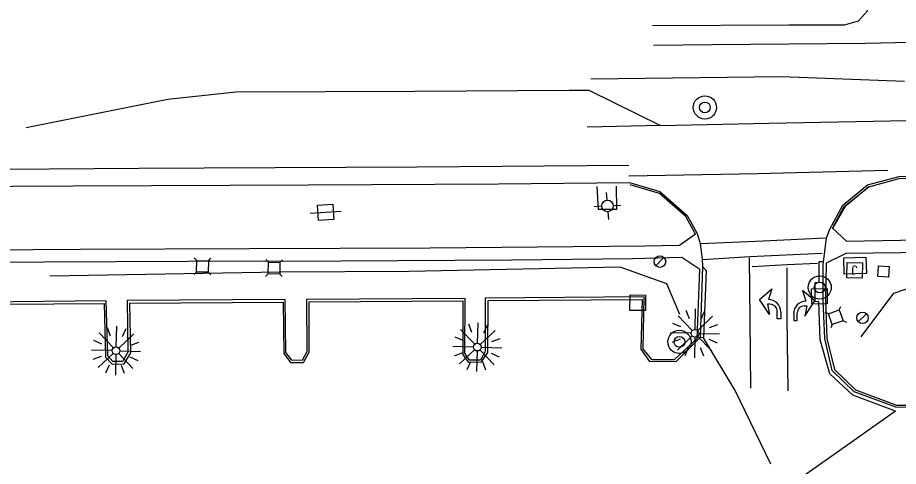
# Model space of a CAD drawing. Extents: x 4711259 to 4716401, y 890074 to 892728.
# Drawn here: x 4711416.6 to 4711702.3, y 891219.7 to 891365.1 of the extents above; entities that cross this region are included whole.
import ezdxf

# ---------------------------------------------------------------- set-up
doc = ezdxf.new("R2010")
doc.units = 0
for name, color, linetype in [('E_HY_STORM_Inlet', 7, 'Continuous'), ('E_HY_STORM_MH', 7, 'Continuous'), ('E_RDWY_ROAD_Curb', 7, 'Continuous'), ('E_RDWY_ROAD_EdgeAsph', 7, 'Continuous'), ('E_RDWY_ROAD_EdgeConc', 7, 'Continuous'), ('E_RDWY_ROAD_Sidewalk', 7, 'Continuous'), ('E_RDWY_ROAD_Striping', 7, 'Continuous'), ('E_RDWY_ROAD_TBofCurb', 7, 'Continuous'), ('E_TERR_DTM_BrkLines', 7, 'Continuous'), ('E_TRAF_ILLUM_Poles', 7, 'Continuous'), ('E_UTIL_COMM_General', 7, 'Continuous'), ('E_UTIL_ELEC_GENERAL', 7, 'Continuous'), ('E_UTIL_ELEC_POLE', 7, 'Continuous'), ('E_UTIL_WTR_General', 7, 'Continuous')]:
    doc.layers.add(name, color=color, linetype=linetype)

msp = doc.modelspace()

# ---------------------------------------------------------------- linework, layer by layer
at = {"layer": 'E_HY_STORM_Inlet'}
for p, q in [((4711676.68, 891274.75), (4711676.68, 891274.75)), ((4711617.76, 891272.68), (4711617.76, 891272.68))]:
    msp.add_line(p, q, dxfattribs=at)
for points in [[(4711674.13, 891277.2), (4711679.13, 891277.3), (4711679.23, 891272.3), (4711674.23, 891272.21)], [(4711615.3, 891275.22), (4711620.3, 891275.13), (4711620.21, 891270.13), (4711615.21, 891270.22)]]:
    msp.add_lwpolyline(points, close=True, dxfattribs=at)
at = {"layer": 'E_HY_STORM_MH'}
for centre, radius in [((4711639.52, 891335.97), 3.75), ((4711639.52, 891335.97), 1.76), ((4711676.75, 891277.63), 3.75), ((4711676.75, 891277.63), 1.76), ((4711631.27, 891260), 3.75), ((4711631.27, 891260), 1.76)]:
    msp.add_circle(centre, radius, dxfattribs=at)
at = {"layer": 'E_RDWY_ROAD_Curb'}
for points in [[(4711677.89, 891285), (4711678.92, 891293.73), (4711680.03, 891296.58), (4711684.3, 891304.36), (4711692.29, 891310.9), (4711702.5, 891313.59), (4711725.75, 891314.23), (4711752.78, 891314.68), (4711806.62, 891316.06), (4711863.71, 891317.72), (4711920.16, 891319.09), (4711978.72, 891320.62), (4712033.32, 891322.35), (4712043.64, 891320.44), (4712051.78, 891316.35), (4712057.43, 891308.73), (4712059.79, 891302.94), (4712060.64, 891297.72), (4712061.23, 891292.43), (4712061.25, 891285.91), (4712059.69, 891272.02), (4712042.09, 891234.96)], [(4711336.39, 891310.08), (4711434.66, 891310.58), (4711510.87, 891310.89), (4711572.62, 891311.17), (4711615.1, 891311.7)], [(4711615.1, 891311.7), (4711624.96, 891308.73), (4711633.75, 891300.95), (4711636.98, 891295.13), (4711637.96, 891291.85), (4711638.62, 891286.7), (4711638.71, 891284.42), (4711637.98, 891261.39), (4711630.13, 891253.52), (4711621.59, 891253.6)], [(4711708.13, 891238.7), (4711701.49, 891238.83), (4711687.96, 891243.76), (4711680.82, 891250.74), (4711678.38, 891261.09), (4711677.88, 891273.18), (4711677.89, 891285)], [(4711395.75, 891272.12), (4711444.67, 891272.45), (4711445.13, 891255.08), (4711447.26, 891252.82), (4711451.17, 891252.94), (4711453.3, 891256.43), (4711453.02, 891272.5), (4711502.79, 891272.88), (4711503.01, 891256.28), (4711505.14, 891253.37), (4711509.38, 891253.31), (4711511.22, 891256.72), (4711511.23, 891273.02), (4711561.06, 891273.28), (4711561, 891255.89), (4711562.79, 891253.43), (4711567.13, 891253.58), (4711569.11, 891256.58), (4711569.24, 891273.42), (4711619.16, 891273.78), (4711618.73, 891257.6), (4711621.59, 891253.6)]]:
    msp.add_lwpolyline(points, dxfattribs=at)
at = {"layer": 'E_RDWY_ROAD_EdgeAsph'}
for points in [[(4711622.49, 891362.56), (4711666.76, 891362.73), (4711684.78, 891362.8), (4711689.34, 891364.01), (4711692.25, 891367.31), (4711693.53, 891374.56), (4711703.95, 891374.38), (4711705.24, 891368.87), (4711709.96, 891362.68), (4711776.96, 891364.6), (4711835.98, 891366.03), (4711881.41, 891367.59), (4711919.85, 891369), (4711975.05, 891370.75), (4712029.86, 891371.24)], [(4711701.39, 891237.5), (4711679.61, 891222.19), (4711662.18, 891210.05), (4711661.02, 891210.07)]]:
    msp.add_lwpolyline(points, dxfattribs=at)
at = {"layer": 'E_RDWY_ROAD_EdgeConc'}
for points in [[(4711610.72, 891310.43), (4711610.84, 891302.85), (4711604.98, 891302.94), (4711604.63, 891310.31)], [(4711638.71, 891284.42), (4711639.99, 891283.15), (4711639.09, 891261.33), (4711637.98, 891261.39)], [(4711701.39, 891237.5), (4711687.47, 891242.73), (4711680.02, 891249.68), (4711676.96, 891260.68), (4711676.52, 891273.03), (4711675.29, 891273.13), (4711675.33, 891279.25), (4711676.55, 891279.34), (4711676.57, 891286.07), (4711677.74, 891286.05)]]:
    msp.add_lwpolyline(points, dxfattribs=at)
msp.add_lwpolyline([(4711691.9, 891282.19), (4711684.72, 891281.98), (4711684.56, 891287.28), (4711691.74, 891287.49)], close=True, dxfattribs=at)
at = {"layer": 'E_RDWY_ROAD_Sidewalk'}
for points in [[(4711680.94, 891296.87), (4711685.45, 891292.66), (4711703.01, 891292.95), (4711756.99, 891293.66), (4711817.64, 891294.79), (4711872.66, 891296.02), (4711927.41, 891297.55), (4711987.49, 891299.53), (4712044.77, 891301.24), (4712054.16, 891301.77), (4712056.9, 891308.38)], [(4712050.78, 891266.23), (4712053.25, 891271.6), (4712055.37, 891280.57), (4712055.29, 891292.27), (4712055, 891297.78), (4712049.68, 891297.66), (4711987.64, 891295.63), (4711929.81, 891293.64), (4711872.89, 891292.06), (4711812.57, 891290.78), (4711757.77, 891289.78), (4711703.21, 891288.9), (4711685.19, 891288.65), (4711678.83, 891285.53)], [(4711636.46, 891294.88), (4711631.24, 891291.26), (4711620.01, 891291.07)], [(4711678.57, 891293.62), (4711658.43, 891292.69), (4711638.33, 891291.79)], [(4711620.01, 891291.07), (4711550.39, 891290.38), (4711491.78, 891290.18), (4711436.87, 891289.98), (4711406.11, 891289.74), (4711362.14, 891289.55)], [(4711620.16, 891287.14), (4711632, 891287.42), (4711637.92, 891283.58)], [(4711638.8, 891286.74), (4711654.11, 891287.68), (4711677.56, 891288.76)], [(4711336.87, 891255.64), (4711335.57, 891258.42), (4711335.29, 891268.88), (4711334.66, 891285.1), (4711401.76, 891285.78), (4711471.79, 891286.18), (4711521.53, 891286.27), (4711576.93, 891286.64), (4711616.2, 891287.07), (4711620.16, 891287.14)]]:
    msp.add_lwpolyline(points, dxfattribs=at)
at = {"layer": 'E_RDWY_ROAD_Striping'}
for p, q in [((4711657.28, 891273.74), (4711661.22, 891277.2)), ((4711661.22, 891277.2), (4711660.13, 891273.73)), ((4711675.13, 891273.25), (4711671.15, 891276.68)), ((4711671.15, 891276.68), (4711672.27, 891273.22)), ((4711660.5, 891268.82), (4711657.28, 891273.74)), ((4711671.95, 891268.31), (4711675.13, 891273.25)), ((4711660.7, 891272.21), (4711659.84, 891272.21)), ((4711659.84, 891272.21), (4711660.5, 891268.82)), ((4711671.72, 891271.69), (4711672.57, 891271.7)), ((4711672.57, 891271.7), (4711671.95, 891268.31)), ((4711662.98, 891267.44), (4711662.98, 891269.92)), ((4711664.12, 891267.44), (4711662.98, 891267.44)), ((4711664.13, 891269.63), (4711664.12, 891267.44)), ((4711668.32, 891269.08), (4711668.34, 891266.89)), ((4711669.48, 891266.91), (4711669.46, 891269.38)), ((4711668.34, 891266.89), (4711669.48, 891266.91))]:
    msp.add_line(p, q, dxfattribs=at)
for points in [[(4712033.23, 891366), (4711976.49, 891364.57), (4711912.7, 891362.48), (4711863.23, 891361.09), (4711806.05, 891359.63), (4711750.14, 891358.03), (4711691.65, 891356.7), (4711641.88, 891356.32), (4711622.85, 891356.1)], [(4711602.05, 891341.43), (4711595.51, 891341.52), (4711545.33, 891341.09), (4711487.42, 891340.98), (4711465.31, 891338.52), (4711419.36, 891329.32)], [(4711602.05, 891341.43), (4711625.17, 891330.14)], [(4711625.17, 891330.14), (4711601.34, 891329.6)], [(4711269.83, 891315.08), (4711322.53, 891315.28), (4711397.46, 891315.84), (4711456.03, 891316.25), (4711477.12, 891316.43), (4711546.25, 891316.78), (4711614.88, 891317.24)], [(4711654.4, 891244.96), (4711654.2, 891267.12), (4711654.03, 891287.21)], [(4711676.09, 891285.4), (4711666.16, 891284.96), (4711654.85, 891284.32)], [(4711666.07, 891284.04), (4711666.11, 891267.61), (4711666.41, 891244.17)]]:
    msp.add_lwpolyline(points, dxfattribs=at)
for centre, radius, start, end in [((4711660.03, 891269.64), 4.1, 359.9112, 88.579), ((4711672.41, 891269.13), 4.1, 91.9545, 180.6222), ((4711660.7, 891269.92), 2.29, 359.9078, 89.9018), ((4711671.74, 891269.41), 2.29, 90.6317, 180.6256)]:
    msp.add_arc(centre, radius, start, end, dxfattribs=at)
at = {"layer": 'E_RDWY_ROAD_TBofCurb'}
for p, q in [((4711692.74, 891310.26), (4711684.89, 891303.73)), ((4711684.89, 891303.73), (4711680.94, 891296.87))]:
    msp.add_line(p, q, dxfattribs=at)
for points in [[(4711680.94, 891296.87), (4711684.71, 891303.85), (4711692.73, 891310.28), (4711702.57, 891312.99), (4711755.12, 891313.91), (4711827.99, 891315.91), (4711883.3, 891317.38), (4711938.22, 891318.67), (4711998.29, 891320.44), (4712033.48, 891321.46), (4712043.24, 891319.87), (4712051.19, 891316)], [(4711636.46, 891294.88), (4711633.35, 891300.64), (4711624.75, 891308.1), (4711615.29, 891310.88)], [(4711678.83, 891285.53), (4711678.61, 891273.44), (4711679.02, 891261.06), (4711681.52, 891251.07), (4711688.38, 891244.51), (4711701.66, 891239.49), (4711707.68, 891239.44), (4711709.96, 891240.83), (4711711.12, 891243.96), (4711711.6, 891259.16), (4711762.73, 891258.56)], [(4711622.28, 891254.31), (4711629.69, 891254.34), (4711636.97, 891261.09), (4711637.92, 891283.58)], [(4711622.28, 891254.31), (4711619.56, 891257.73), (4711619.83, 891274.63), (4711568.22, 891274.18), (4711568.24, 891256.9), (4711566.73, 891254.08), (4711563.18, 891254.03), (4711561.65, 891256.38), (4711561.8, 891274.11), (4711510.27, 891273.75), (4711510.4, 891256.81), (4711508.96, 891254), (4711505.58, 891254.08), (4711503.6, 891256.61), (4711503.42, 891273.7), (4711452.13, 891273.38), (4711452.36, 891256.66), (4711452.37, 891256.65), (4711450.67, 891253.69), (4711447.55, 891253.68), (4711445.89, 891255.53), (4711445.3, 891273.26), (4711394.99, 891272.77)]]:
    msp.add_lwpolyline(points, dxfattribs=at)
at = {"layer": 'E_TERR_DTM_BrkLines'}
for points in [[(4711704.21, 891344.39), (4711664.41, 891345.94), (4711602.57, 891345.09)], [(4711625.17, 891330.14), (4711660.28, 891330.85), (4711705.38, 891331.75)], [(4711698.81, 891315.54), (4711656.55, 891314.47), (4711614.91, 891313.71)], [(4711631.45, 891268.86), (4711627.19, 891278.85), (4711612.04, 891284.17), (4711543.66, 891282.82), (4711501.82, 891282.61), (4711427.09, 891281.33)], [(4711690.22, 891261.69), (4711700.8, 891275.77), (4711716.75, 891281.33), (4711771.69, 891282.14), (4711826.88, 891280.82), (4711878.94, 891280.02), (4711938.44, 891278.06), (4711946.19, 891277.02)], [(4711660.92, 891220.4), (4711649.32, 891244.25), (4711639.09, 891261.33)]]:
    msp.add_lwpolyline(points, dxfattribs=at)
at = {"layer": 'E_TRAF_ILLUM_Poles'}
for p, q in [((4711634.49, 891267.51), (4711633.46, 891270.17)), ((4711636.34, 891264.03), (4711636.46, 891270.7)), ((4711635.45, 891263.68), (4711630.82, 891268.48)), ((4711637.22, 891263.65), (4711642.01, 891268.28)), ((4711638.37, 891267.42), (4711639.52, 891270.02)), ((4711446.79, 891261.87), (4711445.79, 891264.54)), ((4711448.6, 891258.38), (4711448.8, 891265.04)), ((4711563.96, 891263.04), (4711562.97, 891265.71)), ((4711565.77, 891259.55), (4711565.97, 891266.21)), ((4711567.84, 891262.91), (4711569.02, 891265.5)), ((4711631.68, 891264.84), (4711629.08, 891265.99)), ((4711641.04, 891264.61), (4711643.7, 891265.64)), ((4711447.7, 891258.04), (4711443.13, 891262.89)), ((4711449.47, 891257.98), (4711454.32, 891262.56)), ((4711450.67, 891261.74), (4711451.85, 891264.33)), ((4711561.12, 891260.4), (4711558.53, 891261.58)), ((4711564.88, 891259.21), (4711560.31, 891264.06)), ((4711566.64, 891259.15), (4711571.5, 891263.73)), ((4711635.07, 891262.81), (4711628.4, 891262.93)), ((4711635.42, 891261.92), (4711630.62, 891257.29)), ((4711636.29, 891261.53), (4711636.17, 891254.87)), ((4711637.18, 891261.88), (4711641.81, 891257.09)), ((4711637.57, 891262.76), (4711644.23, 891262.64)), ((4711443.95, 891259.23), (4711441.36, 891260.41)), ((4711453.31, 891258.9), (4711455.98, 891259.9)), ((4711570.48, 891260.07), (4711573.15, 891261.07)), ((4711628.93, 891259.93), (4711631.59, 891260.96)), ((4711643.56, 891259.58), (4711640.95, 891260.73)), ((4711447.31, 891257.16), (4711440.65, 891257.36)), ((4711447.65, 891256.27), (4711442.8, 891251.7)), ((4711448.52, 891255.88), (4711448.33, 891249.21)), ((4711449.42, 891256.22), (4711453.99, 891251.37)), ((4711449.81, 891257.09), (4711456.48, 891256.89)), ((4711564.49, 891258.33), (4711557.82, 891258.53)), ((4711558.32, 891255.53), (4711560.99, 891256.52)), ((4711564.83, 891257.44), (4711559.97, 891252.87)), ((4711565.7, 891257.05), (4711565.5, 891250.38)), ((4711566.59, 891257.39), (4711571.17, 891252.54)), ((4711566.98, 891258.26), (4711573.65, 891258.06)), ((4711572.94, 891255.01), (4711570.35, 891256.19)), ((4711633.11, 891255.54), (4711634.26, 891258.15)), ((4711639.17, 891255.4), (4711638.14, 891258.06)), ((4711441.15, 891254.36), (4711443.82, 891255.36)), ((4711455.76, 891253.84), (4711453.18, 891255.02)), ((4711562.45, 891251.09), (4711563.63, 891253.68)), ((4711568.5, 891250.88), (4711567.51, 891253.55)), ((4711445.28, 891249.93), (4711446.46, 891252.51)), ((4711451.33, 891249.71), (4711450.33, 891252.38))]:
    msp.add_line(p, q, dxfattribs=at)
for centre in [(4711636.32, 891262.78), (4711565.74, 891258.3), (4711448.56, 891257.13)]:
    msp.add_circle(centre, 1.25, dxfattribs=at)
at = {"layer": 'E_UTIL_COMM_General'}
msp.add_lwpolyline([(4711699.32, 891284.42), (4711699.07, 891280.93), (4711695.58, 891281.18), (4711695.83, 891284.67)], close=True, dxfattribs=at)
at = {"layer": 'E_UTIL_ELEC_GENERAL'}
msp.add_lwpolyline([(4711685.67, 891285.73), (4711690.67, 891285.64), (4711690.57, 891280.64), (4711685.57, 891280.73)], close=True, dxfattribs=at)
at = {"layer": 'E_UTIL_ELEC_POLE'}
msp.add_line((4711511.54, 891301.68), (4711521.52, 891302.34), dxfattribs=at)
msp.add_lwpolyline([(4711513.87, 891304.34), (4711518.86, 891304.67), (4711519.19, 891299.68), (4711514.2, 891299.35)], close=True, dxfattribs=at)
at = {"layer": 'E_UTIL_WTR_General'}
for p, q in [((4711607.81, 891305.93), (4711607.64, 891308.42)), ((4711609.81, 891304.18), (4711612.3, 891304.36)), ((4711606.07, 891303.93), (4711603.57, 891303.76)), ((4711608.07, 891302.19), (4711608.24, 891299.69)), ((4711626.23, 891287.37), (4711623.65, 891284.65)), ((4711474.75, 891286.36), (4711473.94, 891287.21)), ((4711478.5, 891286.29), (4711479.35, 891287.11)), ((4711497.98, 891285.81), (4711497.16, 891286.66)), ((4711501.72, 891285.74), (4711502.57, 891286.56)), ((4711474.68, 891282.61), (4711473.84, 891281.79)), ((4711478.43, 891282.54), (4711479.25, 891281.69)), ((4711497.91, 891282.06), (4711497.06, 891281.24)), ((4711501.66, 891281.99), (4711502.47, 891281.14)), ((4711683.08, 891270.38), (4711683.58, 891271.45)), ((4711679.56, 891269.1), (4711678.49, 891269.6)), ((4711691.95, 891269.13), (4711689.28, 891266.49)), ((4711680.84, 891265.58), (4711680.34, 891264.51)), ((4711684.36, 891266.86), (4711685.43, 891266.36))]:
    msp.add_line(p, q, dxfattribs=at)
for points in [[(4711478.5, 891286.29), (4711478.43, 891282.54), (4711474.68, 891282.61), (4711474.75, 891286.36)], [(4711501.72, 891285.74), (4711501.66, 891281.99), (4711497.91, 891282.06), (4711497.98, 891285.81)], [(4711680.84, 891265.58), (4711679.56, 891269.1), (4711683.08, 891270.38), (4711684.36, 891266.86)]]:
    msp.add_lwpolyline(points, close=True, dxfattribs=at)
for centre in [(4711607.94, 891304.06), (4711624.94, 891286.01), (4711690.62, 891267.81)]:
    msp.add_circle(centre, 1.87, dxfattribs=at)

# ---------------------------------------------------------------- texts
at = {"layer": 'E_UTIL_ELEC_GENERAL'}
msp.add_text('J', height=3, rotation=178.9007, dxfattribs=at).set_placement((4711689, 891284.74))

doc.saveas('drawing.dxf')
